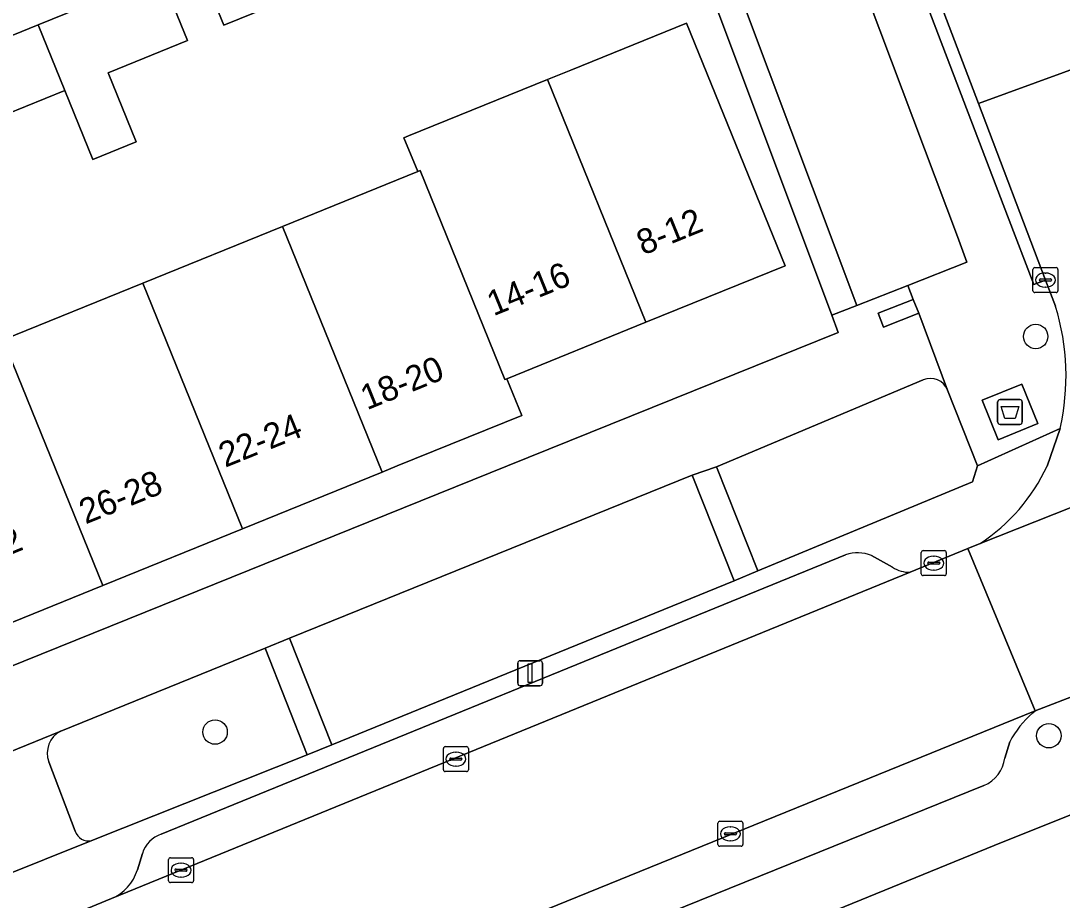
# Model space of a CAD drawing. Extents: x 162989 to 165008, y 383432 to 384338.
# Drawn here: x 163902.79 to 163944.51, y 383982.61 to 384017.83 of the extents above; entities that cross this region are included whole.
import ezdxf

# ---------------------------------------------------------------- set-up
doc = ezdxf.new("R2010")
doc.units = 0
for name, color, linetype in [('IMGEO_Afval_apart_plaats', 7, 'Continuous'), ('IMGEO_Boom', 7, 'Continuous'), ('IMGEO_Erf', 7, 'Continuous'), ('IMGEO_Groenvoorziening', 7, 'Continuous'), ('IMGEO_Kolk', 7, 'Continuous'), ('IMGEO_Lichtmast', 7, 'Continuous'), ('IMGEO_Pand', 7, 'Continuous'), ('IMGEO_Pand_nummerreeks', 7, 'Continuous'), ('IMGEO_Parkeervlak_open', 7, 'Continuous'), ('IMGEO_Rijbaan_lokaal_open', 7, 'Continuous'), ('IMGEO_Terreindeel_gesloten', 7, 'Continuous'), ('IMGEO_Voetpad_gesloten', 7, 'Continuous'), ('IMGEO_Voetpad_open', 7, 'Continuous')]:
    doc.layers.add(name, color=color, linetype=linetype)

msp = doc.modelspace()

# ---------------------------------------------------------------- linework, layer by layer
at = {"layer": 'IMGEO_Afval_apart_plaats'}
for p, q in [((163942.025, 384002.663), (163942.815, 384002.663)), ((163942.815, 384002.663), (163942.025, 384002.663)), ((163941.925, 384001.763), (163941.925, 384002.563)), ((163941.925, 384002.563), (163941.925, 384001.763)), ((163942.915, 384002.563), (163942.915, 384001.763)), ((163942.915, 384001.763), (163942.915, 384002.563)), ((163942.815, 384001.663), (163942.025, 384001.663)), ((163942.025, 384001.663), (163942.815, 384001.663))]:
    msp.add_line(p, q, dxfattribs=at)
msp.add_lwpolyline([(163942.068, 384002.377), (163942.772, 384002.377), (163942.623, 384001.907), (163942.217, 384001.907), (163942.068, 384002.377)], dxfattribs=at)
for centre, start, end in [((163942.025, 384002.563), 90, 180), ((163942.025, 384002.563), 90, 180), ((163942.815, 384002.563), 0, 90), ((163942.815, 384002.563), 360, 90), ((163942.025, 384001.763), 180, 270), ((163942.025, 384001.763), 180, 270), ((163942.815, 384001.763), 270, 0), ((163942.815, 384001.763), 270, 0)]:
    msp.add_arc(centre, 0.1, start, end, dxfattribs=at)
at = {"layer": 'IMGEO_Boom'}
for centre in [(163943.451, 384005.187), (163910.571, 383989.343), (163943.977, 383989.196)]:
    msp.add_circle(centre, 0.489, dxfattribs=at)
at = {"layer": 'IMGEO_Erf'}
for points in [[(163860.657, 383975.132), (163922.286, 384000), (163935.54, 384005.348), (163935.283, 384006.035), (163927.294, 384027.344)], [(163915.736, 384019.618), (163910.914, 384017.661), (163909.854, 384020.271)], [(163908.4, 384019.665), (163909.465, 384017.041), (163906.282, 384015.749), (163907.403, 384012.982), (163905.667, 384012.278), (163904.546, 384015.044), (163899.811, 384013.122)], [(163902.084, 384005.049), (163907.678, 384007.32), (163913.273, 384009.592), (163918.687, 384011.79), (163918.138, 384013.142), (163918.325, 384013.218), (163923.886, 384015.476), (163924.829, 384015.859), (163929.461, 384017.739), (163933.408, 384008.018), (163927.834, 384005.754), (163922.26, 384003.491), (163922.856, 384002.023), (163917.867, 384000), (163917.262, 383999.755), (163911.665, 383997.486), (163906.07, 383995.217), (163900.474, 383992.948)], [(163952.554, 383989.112), (163941.789, 383984.802), (163918.144, 383975.149), (163901.64, 383968.618), (163901.539, 383968.747), (163868.264, 383955.232)]]:
    msp.add_lwpolyline(points, dxfattribs=at)
at = {"layer": 'IMGEO_Groenvoorziening'}
for points in [[(163938.946, 384003.453), (163930.666, 383999.968), (163932.321, 383995.796), (163940.918, 383999.359), (163941.121, 384000), (163939.919, 384003.04)], [(163912.57, 383992.705), (163904.39, 383989.379)], [(163905.625, 383984.998), (163914.265, 383988.432), (163912.57, 383992.705)], [(163903.91, 383988.15), (163904.966, 383985.374)]]:
    msp.add_lwpolyline(points, dxfattribs=at)
msp.add_lwpolyline([(163915.242, 383988.827), (163931.364, 383995.406), (163929.686, 383999.636), (163913.546, 383993.102)], close=True, dxfattribs=at)
for centre, radius, start, end in [((163939.223, 384002.753), 0.753, 22.4194, 111.582), ((163904.828, 383988.5), 0.982, 116.4864, 200.8462), ((163905.494, 383985.534), 0.552, 196.8797, 283.7055)]:
    msp.add_arc(centre, radius, start, end, dxfattribs=at)
at = {"layer": 'IMGEO_Kolk'}
for p, q in [((163943.339, 384007.021), (163943.339, 384007.873)), ((163943.414, 384007.947), (163944.266, 384007.947)), ((163943.827, 384007.727), (163943.852, 384007.727)), ((163944.34, 384007.873), (163944.34, 384007.021)), ((163943.598, 384007.441), (163943.598, 384007.453)), ((163944.036, 384007.404), (163943.638, 384007.404)), ((163943.641, 384007.49), (163944.039, 384007.49)), ((163944.082, 384007.453), (163944.082, 384007.441)), ((163944.266, 384006.947), (163943.414, 384006.947)), ((163943.85, 384007.167), (163943.825, 384007.167)), ((163938.867, 383995.682), (163938.867, 383996.534)), ((163938.942, 383996.608), (163939.794, 383996.608)), ((163939.868, 383996.534), (163939.868, 383995.682)), ((163939.126, 383996.102), (163939.126, 383996.114)), ((163939.564, 383996.065), (163939.166, 383996.065)), ((163939.169, 383996.151), (163939.567, 383996.151)), ((163939.355, 383996.388), (163939.38, 383996.388)), ((163939.61, 383996.114), (163939.61, 383996.102)), ((163939.794, 383995.608), (163938.942, 383995.608)), ((163939.378, 383995.828), (163939.353, 383995.828)), ((163919.72, 383987.833), (163919.72, 383988.685)), ((163919.795, 383988.759), (163920.647, 383988.759)), ((163920.208, 383988.539), (163920.233, 383988.539)), ((163920.721, 383988.685), (163920.721, 383987.833)), ((163919.979, 383988.253), (163919.979, 383988.265)), ((163920.417, 383988.216), (163920.019, 383988.216)), ((163920.022, 383988.302), (163920.42, 383988.302)), ((163920.463, 383988.265), (163920.463, 383988.253)), ((163920.647, 383987.759), (163919.795, 383987.759)), ((163920.231, 383987.979), (163920.206, 383987.979)), ((163930.716, 383984.842), (163930.716, 383985.694)), ((163930.791, 383985.768), (163931.643, 383985.768)), ((163931.204, 383985.548), (163931.229, 383985.548)), ((163931.717, 383985.694), (163931.717, 383984.842)), ((163930.975, 383985.262), (163930.975, 383985.274)), ((163931.413, 383985.225), (163931.015, 383985.225)), ((163931.018, 383985.311), (163931.416, 383985.311)), ((163931.459, 383985.274), (163931.459, 383985.262)), ((163931.643, 383984.768), (163930.791, 383984.768)), ((163931.227, 383984.988), (163931.202, 383984.988)), ((163908.779, 383984.311), (163909.631, 383984.311)), ((163908.704, 383983.385), (163908.704, 383984.237)), ((163909.192, 383984.091), (163909.217, 383984.091)), ((163909.705, 383984.237), (163909.705, 383983.385)), ((163908.963, 383983.805), (163908.963, 383983.817)), ((163909.401, 383983.768), (163909.003, 383983.768)), ((163909.006, 383983.854), (163909.404, 383983.854)), ((163909.215, 383983.531), (163909.19, 383983.531)), ((163909.447, 383983.817), (163909.447, 383983.805)), ((163909.631, 383983.311), (163908.779, 383983.311))]:
    msp.add_line(p, q, dxfattribs=at)
for points in [[(163943.339, 384007.021), (163943.339, 384007.873)], [(163943.414, 384007.947), (163944.266, 384007.947)], [(163944.34, 384007.873), (163944.34, 384007.021)], [(163944.266, 384006.947), (163943.414, 384006.947)], [(163938.867, 383995.682), (163938.867, 383996.534)], [(163938.942, 383996.608), (163939.794, 383996.608)], [(163939.868, 383996.534), (163939.868, 383995.682)], [(163939.794, 383995.608), (163938.942, 383995.608)], [(163919.72, 383987.833), (163919.72, 383988.685)], [(163919.795, 383988.759), (163920.647, 383988.759)], [(163920.721, 383988.685), (163920.721, 383987.833)], [(163920.647, 383987.759), (163919.795, 383987.759)], [(163930.716, 383984.842), (163930.716, 383985.694)], [(163930.791, 383985.768), (163931.643, 383985.768)], [(163931.717, 383985.694), (163931.717, 383984.842)], [(163931.643, 383984.768), (163930.791, 383984.768)], [(163908.779, 383984.311), (163909.631, 383984.311)], [(163908.704, 383983.385), (163908.704, 383984.237)], [(163909.705, 383984.237), (163909.705, 383983.385)], [(163909.631, 383983.311), (163908.779, 383983.311)]]:
    msp.add_lwpolyline(points, dxfattribs=at)
for centre, radius, start, end in [((163943.416, 384007.871), 0.0765, 91.552, 178.448), ((163943.416, 384007.871), 0.0765, 91.552, 178.448), ((163944.264, 384007.871), 0.0765, 1.552, 88.448), ((163944.264, 384007.871), 0.0765, 1.552, 88.448), ((163943.638, 384007.45), 0.0403, 85.8775, 175.7526), ((163943.635, 384007.44), 0.0366, 178.938, 274.7102), ((163944.039, 384007.447), 0.043, 264.8664, 352.4533), ((163944.043, 384007.452), 0.0386, 1.7309, 96.639), ((163943.416, 384007.023), 0.0765, 181.552, 268.448), ((163943.416, 384007.023), 0.0765, 181.552, 268.448), ((163944.264, 384007.023), 0.0765, 271.552, 358.448), ((163944.264, 384007.023), 0.0765, 271.552, 358.448), ((163938.944, 383996.532), 0.0765, 91.552, 178.448), ((163938.944, 383996.532), 0.0765, 91.552, 178.448), ((163939.792, 383996.532), 0.0765, 1.552, 88.448), ((163939.792, 383996.532), 0.0765, 1.552, 88.448), ((163939.166, 383996.111), 0.0403, 85.8775, 175.7526), ((163939.163, 383996.101), 0.0366, 178.938, 274.7102), ((163939.567, 383996.108), 0.043, 264.8664, 352.4533), ((163939.571, 383996.113), 0.0386, 1.7309, 96.639), ((163938.944, 383995.684), 0.0765, 181.552, 268.448), ((163938.944, 383995.684), 0.0765, 181.552, 268.448), ((163939.792, 383995.684), 0.0765, 271.552, 358.448), ((163939.792, 383995.684), 0.0765, 271.552, 358.448), ((163919.797, 383988.683), 0.0765, 91.552, 178.448), ((163919.797, 383988.683), 0.0765, 91.552, 178.448), ((163920.645, 383988.683), 0.0765, 1.552, 88.448), ((163920.645, 383988.683), 0.0765, 1.552, 88.448), ((163920.019, 383988.262), 0.0403, 85.8775, 175.7526), ((163920.016, 383988.252), 0.0366, 178.938, 274.7102), ((163920.42, 383988.259), 0.043, 264.8664, 352.4533), ((163920.424, 383988.264), 0.0386, 1.7309, 96.639), ((163919.797, 383987.835), 0.0765, 181.552, 268.448), ((163919.797, 383987.835), 0.0765, 181.552, 268.448), ((163920.645, 383987.835), 0.0765, 271.552, 358.448), ((163920.645, 383987.835), 0.0765, 271.552, 358.448), ((163930.793, 383985.692), 0.0765, 91.552, 178.448), ((163930.793, 383985.692), 0.0765, 91.552, 178.448), ((163931.641, 383985.692), 0.0765, 1.552, 88.448), ((163931.641, 383985.692), 0.0765, 1.552, 88.448), ((163931.015, 383985.271), 0.0403, 85.8775, 175.7526), ((163931.012, 383985.261), 0.0366, 178.938, 274.7102), ((163931.416, 383985.268), 0.043, 264.8664, 352.4533), ((163931.42, 383985.273), 0.0386, 1.7309, 96.639), ((163930.793, 383984.844), 0.0765, 181.552, 268.448), ((163930.793, 383984.844), 0.0765, 181.552, 268.448), ((163931.641, 383984.844), 0.0765, 271.552, 358.448), ((163931.641, 383984.844), 0.0765, 271.552, 358.448), ((163908.781, 383984.235), 0.0765, 91.552, 178.448), ((163908.781, 383984.235), 0.0765, 91.552, 178.448), ((163909.629, 383984.235), 0.0765, 1.552, 88.448), ((163909.629, 383984.235), 0.0765, 1.552, 88.448), ((163909.003, 383983.814), 0.0403, 85.8775, 175.7526), ((163909, 383983.804), 0.0366, 178.938, 274.7102), ((163909.404, 383983.811), 0.043, 264.8664, 352.4533), ((163909.408, 383983.816), 0.0386, 1.7309, 96.639), ((163908.781, 383983.387), 0.0765, 181.552, 268.448), ((163908.781, 383983.387), 0.0765, 181.552, 268.448), ((163909.629, 383983.387), 0.0765, 271.552, 358.448), ((163909.629, 383983.387), 0.0765, 271.552, 358.448)]:
    msp.add_arc(centre, radius, start, end, dxfattribs=at)
for centre, major_axis, ratio, start_param, end_param in [((163943.826, 384007.447), (-0.387, 0.002), 0.722429, 4.712389, 7.853982), ((163943.851, 384007.447), (-0.39, 0.002), 0.717154, 1.570796, 4.712389), ((163939.354, 383996.108), (-0.387, 0.002), 0.722429, 4.712389, 7.853982), ((163939.379, 383996.108), (-0.39, 0.002), 0.717154, 1.570796, 4.712389), ((163920.207, 383988.259), (-0.387, 0.002), 0.722429, 4.712389, 7.853982), ((163920.232, 383988.259), (-0.39, 0.002), 0.717154, 1.570796, 4.712389), ((163931.203, 383985.268), (-0.387, 0.002), 0.722429, 4.712389, 7.853982), ((163931.228, 383985.268), (-0.39, 0.002), 0.717154, 1.570796, 4.712389), ((163909.191, 383983.811), (-0.387, 0.002), 0.722429, 4.712389, 7.853982), ((163909.216, 383983.811), (-0.39, 0.002), 0.717154, 1.570796, 4.712389)]:
    msp.add_ellipse(centre, major_axis=major_axis, ratio=ratio, start_param=start_param, end_param=end_param, dxfattribs=at)
at = {"layer": 'IMGEO_Lichtmast'}
for p, q in [((163922.695, 383991.297), (163922.695, 383992.097)), ((163922.695, 383992.097), (163922.695, 383991.297)), ((163922.795, 383992.197), (163923.585, 383992.197)), ((163923.585, 383992.197), (163922.795, 383992.197)), ((163923.685, 383992.097), (163923.685, 383991.297)), ((163923.685, 383991.297), (163923.685, 383992.097)), ((163923.585, 383991.197), (163922.795, 383991.197)), ((163922.795, 383991.197), (163923.585, 383991.197))]:
    msp.add_line(p, q, dxfattribs=at)
msp.add_lwpolyline([(163923.115, 383992.072), (163923.265, 383992.072), (163923.265, 383991.322), (163923.115, 383991.322), (163923.115, 383992.072)], dxfattribs=at)
for centre, start, end in [((163922.795, 383992.097), 90, 180), ((163922.795, 383992.097), 90, 180), ((163923.585, 383992.097), 0, 90), ((163923.585, 383992.097), 360, 90), ((163922.795, 383991.297), 180, 270), ((163922.795, 383991.297), 180, 270), ((163923.585, 383991.297), 270, 0), ((163923.585, 383991.297), 270, 0)]:
    msp.add_arc(centre, 0.1, start, end, dxfattribs=at)
at = {"layer": 'IMGEO_Pand'}
for points in [[(163915.736, 384019.618), (163914.679, 384022.23), (163909.854, 384020.271), (163910.914, 384017.661)], [(163908.4, 384019.665), (163903.482, 384017.669), (163904.546, 384015.044), (163905.667, 384012.278), (163907.403, 384012.982), (163906.282, 384015.749), (163909.465, 384017.041)], [(163927.834, 384005.754), (163933.408, 384008.018), (163929.461, 384017.739), (163924.829, 384015.859), (163923.886, 384015.476)], [(163904.546, 384015.044), (163903.482, 384017.669), (163898.746, 384015.746), (163899.811, 384013.122)], [(163923.886, 384015.476), (163918.325, 384013.218), (163918.138, 384013.142), (163918.687, 384011.79), (163918.781, 384011.828), (163922.182, 384003.459), (163922.26, 384003.491), (163927.834, 384005.754)], [(163918.781, 384011.828), (163918.687, 384011.79), (163913.273, 384009.592), (163917.262, 383999.755), (163917.867, 384000), (163922.856, 384002.023), (163922.26, 384003.491), (163922.182, 384003.459)], [(163907.678, 384007.32), (163911.665, 383997.486), (163917.262, 383999.755), (163913.273, 384009.592)], [(163902.084, 384005.049), (163906.07, 383995.217), (163911.665, 383997.486), (163907.678, 384007.32)], [(163902.084, 384005.049), (163896.496, 384002.78), (163899.978, 383994.175), (163900.474, 383992.948), (163906.07, 383995.217)]]:
    msp.add_lwpolyline(points, close=True, dxfattribs=at)
at = {"layer": 'IMGEO_Parkeervlak_open'}
msp.add_lwpolyline([(163932.772, 384029.248), (163928.351, 384027.544), (163936.28, 384006.427), (163938.328, 384007.232), (163940.698, 384008.164), (163940.314, 384009.185)], close=True, dxfattribs=at)
for points in [[(163935.834, 383996.442), (163908.415, 383985.25)], [(163937.715, 383995.941), (163936.875, 383996.408)], [(163906.416, 383982.671), (163938.425, 383995.742)], [(163943.33, 383990.107), (163943.426, 383990.186), (163908.034, 383975.808), (163905.486, 383974.773), (163903.966, 383974.155)], [(163942.21, 383988.302), (163942.41, 383988.95)], [(163907.263, 383973.414), (163941.375, 383987.207)], [(163907.656, 383984.473), (163907.455, 383983.825)]]:
    msp.add_lwpolyline(points, dxfattribs=at)
for centre, radius, start, end in [((163936.309, 383995.047), 1.474, 67.4394, 108.8193), ((163938.399, 383997.014), 1.272, 237.4947, 271.1909), ((163945.831, 383987.174), 3.854, 130.4542, 152.5652), ((163940.887, 383988.445), 1.331, 291.5236, 353.8213), ((163908.795, 383984.119), 1.193, 108.5843, 162.7585), ((163905.717, 383984.345), 1.814, 292.6644, 343.3392)]:
    msp.add_arc(centre, radius, start, end, dxfattribs=at)
at = {"layer": 'IMGEO_Rijbaan_lokaal_open'}
for points in [[(163902.699, 384136.428), (163902.42, 384136.156), (163900.713, 384134.073), (163899.073, 384131.221), (163898.552, 384127.219), (163903.65, 384113.577), (163905.658, 384108.202), (163908.244, 384101.283), (163909.453, 384098.047), (163932.403, 384037.527), (163941.155, 384014.522), (163945.705, 384016.169), (163943.363, 384022.339), (163928.089, 384062.572), (163925.404, 384069.644), (163909.585, 384111.313)], [(163948.608, 384008.523), (163947.266, 384012.058), (163945.705, 384016.169), (163941.155, 384014.522), (163943.847, 384007.446), (163944.247, 384006.394)], [(163941.227, 383996.897), (163958.953, 384003.914)], [(163944.428, 384001.499), (163943.911, 383999.998)]]:
    msp.add_lwpolyline(points, dxfattribs=at)
for points in [[(163961.684, 383997.251), (163960.624, 384000), (163959.093, 384003.969), (163958.953, 384003.914), (163941.227, 383996.897), (163940.738, 383996.695), (163943.426, 383990.186), (163947.029, 383991.58), (163950.595, 383992.96)], [(163943.426, 383990.186), (163940.738, 383996.695), (163938.425, 383995.742), (163906.416, 383982.671), (163905.412, 383982.265), (163908.034, 383975.808)]]:
    msp.add_lwpolyline(points, close=True, dxfattribs=at)
for centre, radius, start, end in [((163935.211, 384003.609), 9.455, 347.1054, 17.1298), ((163937.078, 384003.2), 7.546, 303.3549, 334.891)]:
    msp.add_arc(centre, radius, start, end, dxfattribs=at)
at = {"layer": 'IMGEO_Terreindeel_gesloten'}
msp.add_lwpolyline([(163938.767, 384006.115), (163938.547, 384006.674), (163937.132, 384006.117), (163937.352, 384005.559)], close=True, dxfattribs=at)
at = {"layer": 'IMGEO_Voetpad_gesloten'}
msp.add_lwpolyline([(163942.894, 384003.277), (163941.304, 384002.63), (163941.947, 384001.049), (163943.537, 384001.696)], close=True, dxfattribs=at)
at = {"layer": 'IMGEO_Voetpad_open'}
for points in [[(163944.247, 384006.394), (163943.847, 384007.446), (163943.376, 384007.266), (163942.325, 384010.017), (163931.891, 384037.332), (163932.403, 384037.527), (163909.453, 384098.047)], [(163920.867, 384060.492), (163923.18, 384054.38), (163930.377, 384035.386), (163932.083, 384030.999), (163926.74, 384028.823), (163926.713, 384028.812), (163927.294, 384027.344), (163935.283, 384006.035), (163936.28, 384006.427), (163928.351, 384027.544), (163932.772, 384029.248), (163940.314, 384009.185), (163940.698, 384008.164), (163938.328, 384007.232), (163938.547, 384006.674), (163938.767, 384006.115), (163939.919, 384003.04), (163941.121, 384000), (163944.428, 384001.499)], [(163857.577, 383994.229), (163860.357, 383985.804), (163862.225, 383986.559), (163861.551, 383988.223), (163858.852, 383996.609), (163857.798, 383999.214), (163859.746, 384000), (163862.092, 384000.947), (163863.492, 384001.512), (163868.392, 384003.49), (163873.22, 384005.438), (163874.611, 384006), (163879.788, 384008.089), (163884.385, 384009.944), (163885.785, 384010.509), (163890.765, 384012.519), (163892.18, 384013.09), (163897.293, 384015.166), (163898.746, 384015.746), (163903.482, 384017.669), (163908.4, 384019.665)], [(163939.919, 384003.04), (163938.767, 384006.115), (163937.352, 384005.559), (163937.132, 384006.117), (163938.547, 384006.674), (163938.328, 384007.232), (163936.28, 384006.427), (163935.283, 384006.035), (163935.54, 384005.348), (163922.286, 384000), (163860.657, 383975.132)], [(163861.708, 383972.246), (163869.582, 383975.37), (163870.491, 383975.736), (163889.739, 383983.483), (163890.546, 383983.807), (163899.886, 383987.554), (163904.39, 383989.379), (163912.57, 383992.705), (163913.546, 383993.102), (163929.686, 383999.636), (163930.666, 383999.968), (163938.946, 384003.453)], [(163943.911, 383999.998), (163944.428, 384001.499), (163941.121, 384000), (163940.918, 383999.359), (163932.321, 383995.796), (163931.364, 383995.406), (163915.242, 383988.827), (163914.265, 383988.432), (163905.625, 383984.998), (163901.827, 383983.48), (163892.281, 383979.552), (163891.415, 383979.207), (163872.224, 383971.398), (163871.367, 383971.048), (163865.192, 383968.522), (163866.079, 383966.355), (163866.224, 383966.406), (163866.484, 383966.516)], [(163867.106, 383954.34), (163868.264, 383955.232), (163901.539, 383968.747), (163901.64, 383968.618), (163918.144, 383975.149), (163941.789, 383984.802), (163952.554, 383989.112), (163962.348, 383993.055), (163980.091, 384000)], [(163965.51, 383997.511), (163964.798, 383997.915), (163964.117, 383998.113), (163963.995, 383998.11), (163963.895, 383998.107), (163961.684, 383997.251), (163950.595, 383992.96), (163950.775, 383992.495), (163947.209, 383991.114), (163947.029, 383991.58), (163943.426, 383990.186), (163943.33, 383990.107)], [(163938.425, 383995.742), (163940.738, 383996.695), (163941.227, 383996.897)], [(163908.415, 383985.25), (163935.834, 383996.442)], [(163936.875, 383996.408), (163937.715, 383995.941)], [(163904.39, 383989.379), (163899.886, 383987.554)], [(163942.41, 383988.95), (163942.21, 383988.302)], [(163904.966, 383985.374), (163903.91, 383988.15)], [(163941.375, 383987.207), (163907.263, 383973.414)], [(163901.827, 383983.48), (163905.625, 383984.998)], [(163907.455, 383983.825), (163907.656, 383984.473)], [(163902.71, 383981.172), (163902.862, 383981.233), (163905.412, 383982.265), (163906.416, 383982.671)]]:
    msp.add_lwpolyline(points, dxfattribs=at)
for points in [[(163932.403, 384037.527), (163931.891, 384037.332), (163942.325, 384010.017), (163943.376, 384007.266), (163943.847, 384007.446), (163941.155, 384014.522)], [(163942.894, 384003.277), (163943.537, 384001.696), (163941.947, 384001.049), (163941.304, 384002.63)], [(163930.666, 383999.968), (163929.686, 383999.636), (163931.364, 383995.406), (163932.321, 383995.796)], [(163913.546, 383993.102), (163912.57, 383992.705), (163914.265, 383988.432), (163915.242, 383988.827)]]:
    msp.add_lwpolyline(points, close=True, dxfattribs=at)
for centre, radius, start, end in [((163935.211, 384003.609), 9.455, 347.1054, 17.1298), ((163939.223, 384002.753), 0.753, 22.4194, 111.582), ((163937.078, 384003.2), 7.546, 303.3549, 334.891), ((163936.309, 383995.047), 1.474, 67.4394, 108.8193), ((163938.399, 383997.014), 1.272, 237.4947, 271.1909), ((163945.831, 383987.174), 3.854, 130.4542, 152.5652), ((163904.828, 383988.5), 0.982, 116.4864, 200.8462), ((163940.887, 383988.445), 1.331, 291.5236, 353.8213), ((163905.494, 383985.534), 0.552, 196.8797, 283.7055), ((163908.795, 383984.119), 1.193, 108.5843, 162.7585), ((163905.717, 383984.345), 1.814, 292.6644, 343.3392)]:
    msp.add_arc(centre, radius, start, end, dxfattribs=at)

# ---------------------------------------------------------------- texts
at = {"layer": 'IMGEO_Pand_nummerreeks'}
for s, rotation, p in [('8-12', 22.1056, (163927.719, 384008.427)), ('14-16', 22.099, (163921.724, 384005.993)), ('18-20', 22.0703, (163916.656, 384002.228)), ('22-24', 22.071, (163910.972, 383999.924)), ('26-28', 22.071, (163905.379, 383997.656)), ('30-32', 22.071, (163899.775, 383995.384))]:
    msp.add_text(s, height=1, rotation=rotation, dxfattribs=at).set_placement(p)

doc.saveas('drawing.dxf')
